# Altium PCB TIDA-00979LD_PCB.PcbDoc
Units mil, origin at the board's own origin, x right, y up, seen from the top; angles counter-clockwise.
Board outline 1000 x 1000 mil, 2 copper layers (Top Layer, Bottom Layer), stack 62 mil thick; 31 components, 45 nets, 126 pads, 53 vias.
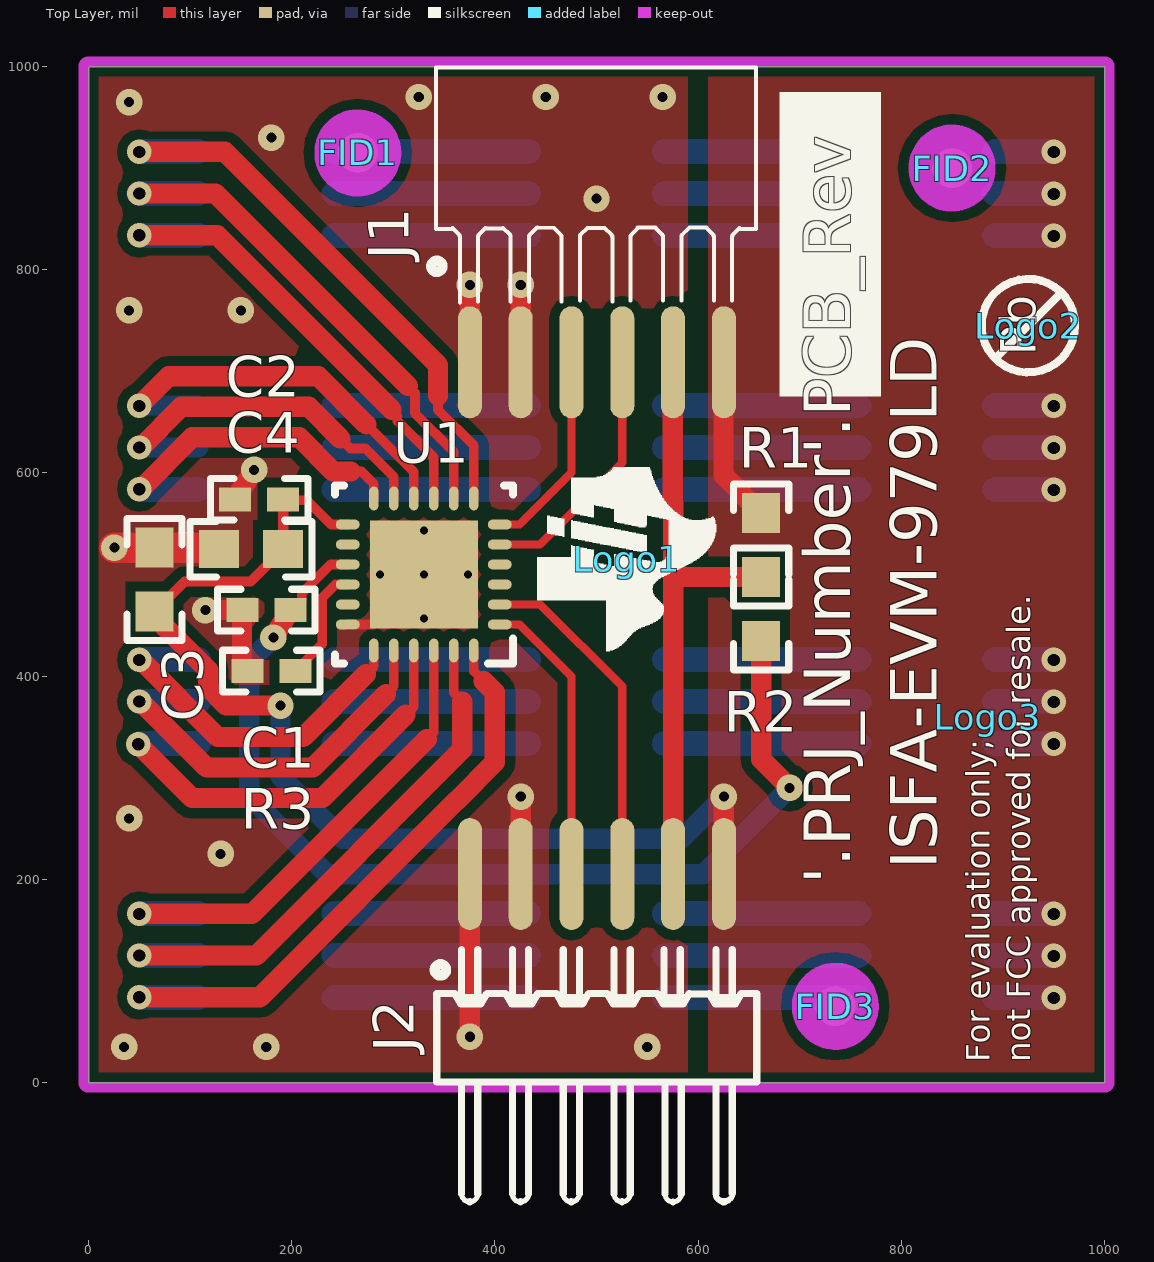
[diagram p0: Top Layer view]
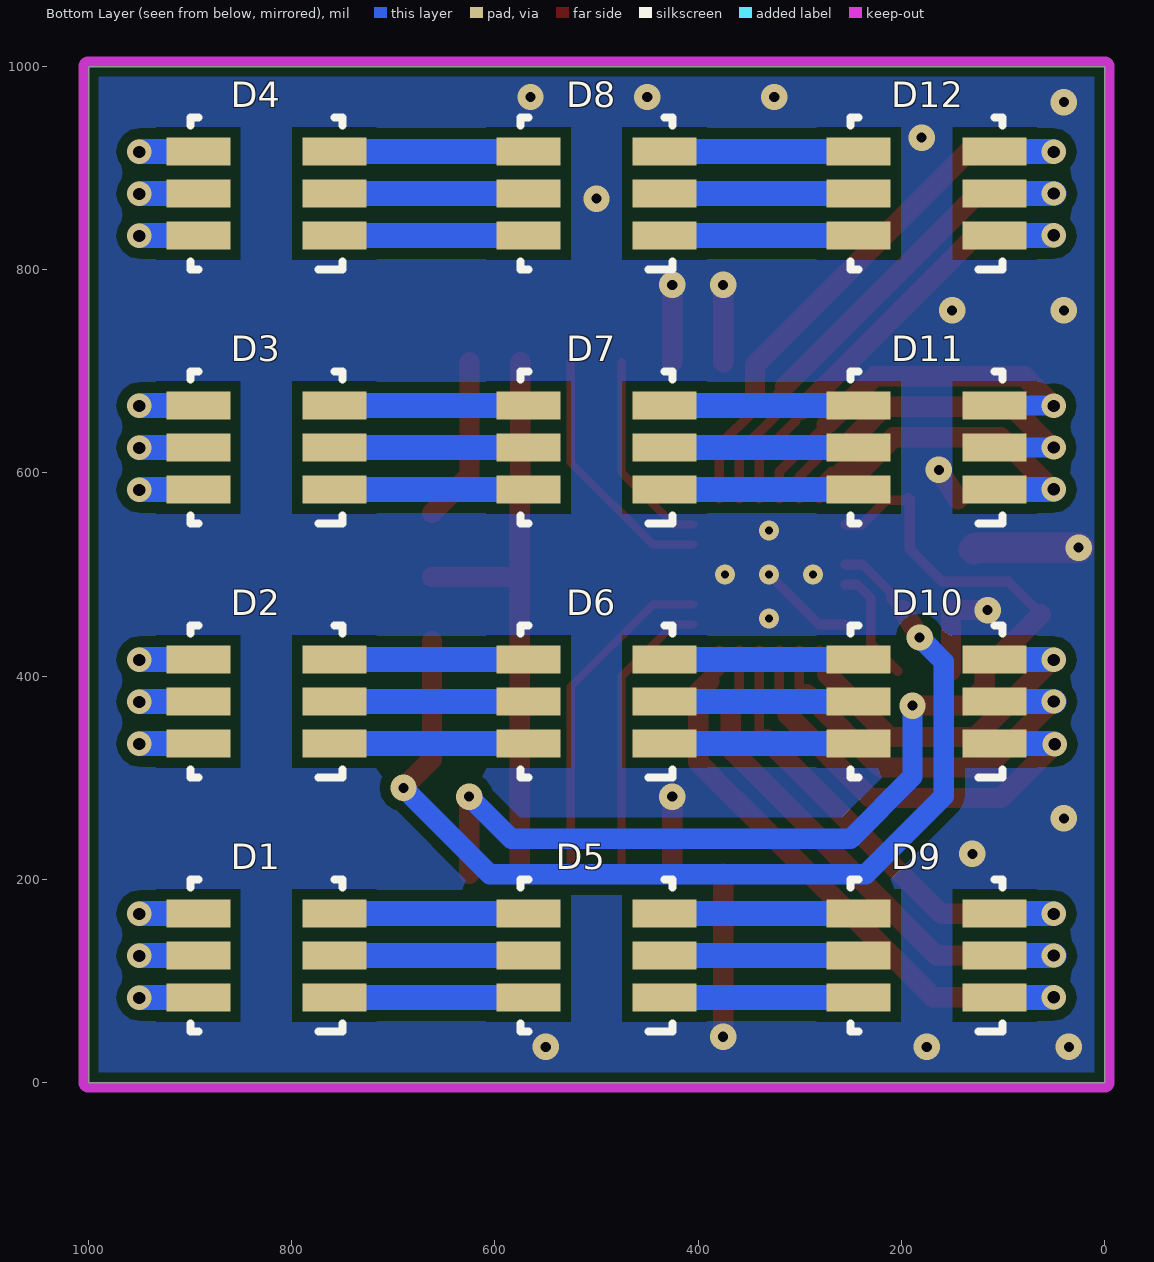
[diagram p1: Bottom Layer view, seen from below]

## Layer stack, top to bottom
Top Solder: solder mask 0.4, Solder Resist, Dk 3.5
Top Layer: signal copper 1.4
Dielectric1: core 59.2, FR-4, Dk 4.8
Bottom Layer: signal copper 1.4
Bottom Solder: solder mask 0.4, Solder Resist, Dk 3.5

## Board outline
0,0 1000,0 1000,1000 0,1000

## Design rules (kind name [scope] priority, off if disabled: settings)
AcuteAngle [All] p1: minimum=4.50000000000000E+0001 checktracksonly=FALSE
AssemblyTestPointUsage [All] p1: valid=2
Clearance Clearance_Keepouts [((IsTrack Or IsArc) And Not InPoly) And IsFree and IsKeepOut vs ((IsTrack Or IsArc) And Not InPoly) And IsFree and IsKeepOut] p1: gap=0
Clearance Clearance_Poly [InPolygon] p2: gap=25 except(10: Arc-Poly Track-Poly SMDPad-Poly Via-Poly Fill-Poly Poly-Poly)
Clearance [All] p3: gap=7.87
ComponentClearance ComponentClearance_3PIN_RES [incomponent('R1') or incomponent('R2') vs incomponent('R1') or incomponent('R2')] p1: gap=0 collisioncheckmode=3 verticalgap=0 showdistances=FALSE
ComponentClearance ComponentClearance_MountingHoles_FiducialMarks [InComponentClass('Mounting Holes') vs InComponentClass('FiducialMark')] p2: gap=50 collisioncheckmode=3 verticalgap=10 showdistances=FALSE
ComponentClearance ComponentClearance_Shunt [InComponentClass('Header') vs InComponentClass('Shunt')] p3: gap=0 collisioncheckmode=3 verticalgap=0 showdistances=FALSE
ComponentClearance ComponentClearance_Logo [InComponentClass('Logo')] p4: gap=25 collisioncheckmode=3 verticalgap=10 showdistances=FALSE
ComponentClearance ComponentClearance_ScrewToNut [(HasFootprint('NY PMS 440 0025 PH')) vs (HasFootprint('Keystone_1902C'))] p5: gap=5 collisioncheckmode=3 verticalgap=10 showdistances=FALSE
ComponentClearance ComponentClearance_MountingHoles [InComponentClass('Mounting Holes')] p6: gap=250 collisioncheckmode=3 verticalgap=100000 showdistances=FALSE
ComponentClearance ComponentClearance_SmallPassives [HasFootprint('0201*') or HasFootprint('0402*') or HasFootprint('0508') or HasFootprint('0603*') or HasFootprint('0612') or HasFootprint('0805*') or HasFootprint('0815*') or HasFootprint('0830*') or HasFootprint('1206*') or HasFootprint('1210*') or HasFootprint('1808*') or HasFootprint('1812*') or HasFootprint('1825*') or HasFootprint('2010*') or HasFootprint('2220*') or HasFootprint('2225*') or HasFootprint('2512*') or HasFootprint('2728*') or HasFootprint('3518*') vs HasFootprint('0201*') or HasFootprint('0402*') or HasFootprint('0508') or HasFootprint('0603*') or HasFootprint('0612') or HasFootprint('0805*') or HasFootprint('0815*') or HasFootprint('0830*') or HasFootprint('1206*') or HasFootprint('1210*') or HasFootprint('1808*') or HasFootprint('1812*') or HasFootprint('1825*') or HasFootprint('2010*') or HasFootprint('2220*') or HasFootprint('2225*') or HasFootprint('2512*') or HasFootprint('2728*') or HasFootprint('3518*')] p7: gap=14.96 collisioncheckmode=3 verticalgap=10 showdistances=FALSE
ComponentClearance ComponentClearance_THtoSMT [IsThruComponent vs IsSMTComponent] p8: gap=40 collisioncheckmode=3 verticalgap=30 showdistances=FALSE
ComponentClearance ComponentClearance_THtoTH [IsThruComponent vs IsThruComponent] p9: gap=30 collisioncheckmode=3 verticalgap=30 showdistances=FALSE
ComponentClearance [All] p10: gap=30 collisioncheckmode=3 verticalgap=10 showdistances=FALSE
DiffPairsRouting [All] p1: maxlimit=100 minlimit=10 mostfreqgap=10 toplayer_minwidth=15 toplayer_maxwidth=15 toplayer_prefwidth=15 bottomlayer_minwidth=15 bottomlayer_maxwidth=15 bottomlayer_prefwidth=15 maxuncoupledlength=1000
FabricationTestPointUsage TestPointUsage [All] p1: valid=2 allowmultiple=FALSE
FabricationTestpoint Testpoint [All] p1: side=3 testpointundercomponent=TRUE minsize=40 maxsize=100 preferedsize=60 minholesize=0 maxholesize=40 preferedholesize=32 testpointgrid=1 allowsidetop=TRUE allowsidebottom=TRUE usegrid=TRUE gridtolerance=0.01
FanoutControl Fanout_LCC [IsLCC] p1: bgadir=Out bgaviamode=Centered fanoutstyle=Auto fanoutdirection=Alternating viagrid=1 // Fanout_LCC (Default Rule)
FanoutControl Fanout_BGA [IsBGA] p2: bgadir=Out bgaviamode=Centered fanoutstyle=Auto fanoutdirection=Alternating viagrid=1 // Fanout_BGA (Default Rule)
FanoutControl Fanout_Default [All] p4: bgadir=Out bgaviamode=Centered fanoutstyle=Auto fanoutdirection=Alternating viagrid=1 // Fanout_Default (Default Rule)
FanoutControl Fanout_Small [(CompPinCount < 5)] p5: bgadir=Out bgaviamode=Centered fanoutstyle=Auto fanoutdirection=OutThenIn viagrid=1 // Fanout_Small (Default Rule)
HoleSize [All] p1: absolutevalues=TRUE maxlimit=251 minlimit=7.87 maxpercent=80.000 minpercent=20.000
MinimumAnnularRing MinimumAnnularRing_ThermalPadVias [IsVia and InAnyComponent] p1: minimumring=5.91
MinimumAnnularRing [All] p2: minimumring=6
MinimumSolderMaskSliver MinimumSolderMaskSliver_Logo [InComponentClass('Logo') vs InComponentClass('Logo')] p1: minsoldermaskwidth=0.7
MinimumSolderMaskSliver [All] p2: minsoldermaskwidth=3.94
PlaneConnect [All] p1: planeconnectstyle=Direct reliefexpansion=10 reliefentries=4 reliefconductorwidth=10 reliefairgap=10
PolygonConnect PolygonConnect_1 [All vs IsNamedPolygon('TOP_LAYER_NETD12_3_P002')] p1: connectstyle=Direct reliefconductorwidth=10 reliefentries=4 polygonreliefangle="90 Angle" airgapwidth=10
PolygonConnect [All] p2: connectstyle=Direct reliefconductorwidth=10 reliefentries=4 polygonreliefangle="90 Angle" airgapwidth=10
RoutingVias ThermalPadVias [IsVia and InAnyComponent] p1: holewidth=7.87 width=19.68 viastyle="Through Hole" minholewidth=7.87 minwidth=19.68 maxholewidth=12.99 maxwidth=23.62
RoutingVias [All] p2: holewidth=16 width=34 viastyle="Through Hole" minholewidth=7.87 minwidth=24 maxholewidth=40 maxwidth=65
SilkToBoardRegionClearance [Not ((IsComment or IsDesignator) And (Hide <> 'False')) and not InRegion(1000,500,4000,800)] p1:
SilkToSilkClearance SilkToSilkClearance_Pb-FreeLogo [(HasFootprint('Pb-Free_Overlay_Medium') OR HasFootprint('Pb-Free_Overlay_Small')) vs (HasFootprint('Pb-Free_Overlay_Medium') OR HasFootprint('Pb-Free_Overlay_Small'))] p1: silktosilkclearance=0
SilkToSilkClearance [All] p2: silktosilkclearance=4
SilkToSolderMaskClearance SilkToComponentPadClearance [IsPad and InAnycomponent] p1: minsilkscreentomaskgap=4.73 clearancetoexposedcopper=TRUE
SilkToSolderMaskClearance "Silk to Solder Mask Opening" [All] p2: minsilkscreentomaskgap=4 clearancetoexposedcopper=FALSE
SolderMaskExpansion [All] p1: expansion=1.97
Width [All] p1: maxlimit=100 minlimit=6 preferedwidth=10 checkconnectedcopper=TRUE
15 further rules are at their usual default settings.

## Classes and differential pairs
component class AssemblyNote: ZZ1 ZZ2 ZZ3
component class FiducialMark: FID1 FID2 FID3
component class TIDA-00979LD_CoverSheet: FID1 FID2 FID3 Logo1 Logo2 Logo3 ZZ1 ZZ2 ZZ3
component class Logo: Logo1
component class TIDA-00979LD_LEDdriver: C1 C2 C3 C4 D1 D2 D3 D4 D5 D6 D7 D8 D9 D10 D11 D12 J1 J2 R1 R2 R3 U1

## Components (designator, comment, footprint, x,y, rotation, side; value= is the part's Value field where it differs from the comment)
C1 "GRM155R70J105MA12D" 0402 175,465 r180 top
C2 "GRM155R71E104KE14D" 0402 168,574 r180 top
C3 "C1608X5R1E106M080AC" 0603 65,495 r90 top
C4 "C1608X5R1E106M080AC" 0603 160,525 r180 top
D1 "CLX6C-FKB-CGJKNCFBB789363" CLX6C-FKB_RGB 825,125 r0 bottom
D2 "CLX6C-FKB-CGJKNCFBB789363" CLX6C-FKB_RGB 825,375 r0 bottom
D3 "CLX6C-FKB-CGJKNCFBB789363" CLX6C-FKB_RGB 825,625 r0 bottom
D4 "CLX6C-FKB-CGJKNCFBB789363" CLX6C-FKB_RGB 825,875 r0 bottom
D5 "CLX6C-FKB-CGJKNCFBB789363" CLX6C-FKB_RGB 500,125 r0 bottom
D6 "CLX6C-FKB-CGJKNCFBB789363" CLX6C-FKB_RGB 500,375 r0 bottom
D7 "CLX6C-FKB-CGJKNCFBB789363" CLX6C-FKB_RGB 500,625 r0 bottom
D8 "CLX6C-FKB-CGJKNCFBB789363" CLX6C-FKB_RGB 500,875 r0 bottom
D9 "CLX6C-FKB-CGJKNCFBB789363" CLX6C-FKB_RGB 175,125 r0 bottom
D10 "CLX6C-FKB-CGJKNCFBB789363" CLX6C-FKB_RGB 175,375 r0 bottom
D11 "CLX6C-FKB-CGJKNCFBB789363" CLX6C-FKB_RGB 175,625 r0 bottom
D12 "CLX6C-FKB-CGJKNCFBB789363" CLX6C-FKB_RGB 175,875 r0 bottom
FID1 "Fiducial" Fiducial10-20 265,915 r0 top
FID2 "Fiducial" Fiducial10-20 850,900 r0 top
FID3 "Fiducial" Fiducial10-20 735,75 r0 top
J1 "851-11-006-40-001000" Mill-Max_851-11-006-40-001000 500.39,890 r90 top
J2 "850-10-006-40-001000" Mill-Max_850-10-006-40-001000 475,43.9 r0 top
Logo1 "Texas Instruments" TI_Symbol_Overlay_Small 530,515 r90 top
Logo2 "Pb-Free Symbol" Pb-Free_Overlay_Small 925,745 r90 top
Logo3 "FCC disclaimer" FCC_disclaimer_stacked 885,360 r90 top
R1 "CRCW06030000Z0EA" 0603 662,529 r90 top
R2 "CRCW06030000Z0EA" 0603 662,466 r270 top
R3 "CRCW04021K60JNED" 0402 180,405 r180 top
U1 "TLC5971RGER" RGE0024H 330,500 r180 top
ZZ1 "These assemblies are ESD sensitive, ESD precautions shall be observed." AssemblyNote 200,1350 r0 top
ZZ2 "These assemblies must be clean and free from flux and all contaminants. Use of no clean flux is not acceptable." AssemblyNote 200,1250 r0 top
ZZ3 "These assemblies must comply with workmanship standards IPC-A-610 Class 2, unless otherwise specified." AssemblyNote 200,1150 r0 top

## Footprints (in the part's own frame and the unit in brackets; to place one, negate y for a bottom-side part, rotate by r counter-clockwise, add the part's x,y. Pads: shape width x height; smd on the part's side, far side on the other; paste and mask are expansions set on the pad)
0402 [mm] "0402 from SM-752 data"
  rect 0.8x0.6 smd: 1(-0.6,0) 2(0.6,0)
  silkscreen extent -1.22,-0.52 1.22,0.52, body extent -0.55,-0.3 0.55,0.3, height 0.6
0603 [mm] "0603 from SM-752 data"
  rect 1x0.95 smd: 1(-0.8,0) 2(0.8,0)
  silkscreen extent -1.52,-0.69 1.52,0.69, body extent -0.87,-0.47 0.87,0.47, height 1
AssemblyNote [mil] "Assembly Note"
CLX6C-FKB_RGB [mm] "SMD, 6-Leads, Body 3.4x3.4mm"
  rect 1.6x0.7 smd: 1(-1.7,1.05) 2(-1.7,0) 3(-1.7,-1.05) 4(1.7,-1.05) 5(1.7,0) 6(1.7,1.05)
  silkscreen extent -1.9,-1.9 1.9,1.9, body extent -1.8,-1.75 1.8,1.75, height 2.9
FCC_disclaimer_stacked [mil]
Fiducial10-20 [mm]
  round 1 smd mask+0.5: 1(0,0)
  Top Layer keep-out circle w1.178: c0,0 r0.5
Mill-Max_850-10-006-40-001000 [mm] "Mill-max"
  oval 0.6x2.8 smd: 1(-2.53,4.1) 2(-1.26,4.1) 3(0.01,4.1) 4(1.28,4.1) 5(2.55,4.1) 6(3.82,4.1)
  silkscreen extent -3.41,-4.1 4.64,2.21, body extent -3.36,-4.08 4.64,5.44, height 2.15
Mill-Max_851-11-006-40-001000 [mm] "Mill-max"
  oval 2.8x0.6 smd: 1(-4.6,3.175) 2(-4.6,1.905) 3(-4.6,0.635) 4(-4.6,-0.635) 5(-4.6,-1.905) 6(-4.6,-3.175)
  silkscreen extent -3.1,-3.98 2.77,4.14, body extent -5.96,-4 2.77,4.01, height 2.03
Pb-Free_Overlay_Small [mil]
  silkscreen extent -46,-46 46,46
RGE0024H [mm] "QFN, 24-Leads, Body 4x4mm, Pitch 0.5mm, Thermal Pad 2.7x2.7mm, TI Recommended"
  oval 0.6x0.24 smd: 1(-1.9,1.25) 2(-1.9,0.75) 3(-1.9,0.25) 4(-1.9,-0.25) 5(-1.9,-0.75) 6(-1.9,-1.25) 13(1.9,-1.25) 14(1.9,-0.75) 15(1.9,-0.25) 16(1.9,0.25) 17(1.9,0.75) 18(1.9,1.25)
  oval 0.24x0.6 smd: 7(-1.25,-1.9) 8(-0.75,-1.9) 9(-0.25,-1.9) 10(0.25,-1.9) 11(0.75,-1.9) 12(1.25,-1.9) 19(1.25,1.9) 20(0.75,1.9) 21(0.25,1.9) 22(-0.25,1.9) 23(-0.75,1.9) 24(-1.25,1.9)
  rect 2.7x2.7 smd paste-1.35: 25(0,0)
  silkscreen extent -2.22,-2.22 2.22,2.22, body extent -2.07,-2.07 2.07,2.07, height 1.01
TI_Symbol_Overlay_Small [mil]
  silkscreen extent -90,-88 91,88

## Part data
C1: "CAP, CERM, 1 µF, 6.3 V, +/- 20%, X7R, 0402"
C2: "CAP, CERM, 0.1 µF, 25 V, +/- 10%, X7R, 0402"
C3 C4: "CAP, CERM, 10 µF, 25 V, +/- 20%, X5R, 0603"
D1 D2 D3 D4 D5 D6 D7 D8 D9 D10 D11 D12: "LED, Rgb, SMD"
FID1 FID2 FID3: "Fiducial mark.  There is nothing to buy or mount."
J1: "Receptacle, 50mil, 5x1, Gold, R/A, SMT"
J2: "Header, 50mil, 6x1, Gold, R/A, SMT"
Logo1: library part TI_Logo, "Texas Instrument Corporate Signature"
Logo2: library part Pb-Free
Logo3: library part FCC_disclaimer, "FCC_disclaimer"
R1 R2: "RES, 0, 5%, 0.1 W, 0603"
R3: "RES, 1.6 k, 5%, 0.063 W, 0402"
U1: "12-Channel, 16-Bit ES-PWM RGB LED Driver with 3.3 V Linear Regulator, 6 to 17 V, -40 to 85 degC, 24-pin QFN (RGE24), Green (RoHS & no Sb/Br)"
ZZ1 ZZ2 ZZ3: library part AssemblyNote

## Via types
v1: diameter 24, hole 12, Top Layer to Bottom Layer, tented both sides, 24 vias
v2: diameter 26, hole 10, Top Layer to Bottom Layer, tented both sides, 24 vias
v3: diameter 19.68, hole 7.87, Top Layer to Bottom Layer, 5 vias

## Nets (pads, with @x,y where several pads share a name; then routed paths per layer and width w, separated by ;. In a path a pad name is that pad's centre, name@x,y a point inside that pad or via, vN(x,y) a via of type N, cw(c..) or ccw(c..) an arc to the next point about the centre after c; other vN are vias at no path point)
GND: C1.2 C2.2 C3.2 C4.2 J1.1 J1.2 J2.1 J2.2 R3.2 U1.18 U1.25 | length 718.4
  Top Layer w9.5: U1.18 280.79,450.79 v3(330,500)
  Top Layer w20: v2(115,465) C1.2@151.13,465 ; C2.2 v2(163,603) ; R3.2@151.38,405 151.13,405.25 C1.2@151.13,465 ; C1.2 C1.2@151.13,465 ; v2(375.39,45) J2.1 ; J1.1 v2(375.39,785) ; J2.2 v2(425.39,281.42) ; J1.2 v2(425.39,785)
  Top Layer w30: v2(25.5,526.5) C3.2 127.01,526.5 C4.2
  other v2: 35,35 175,35 550,35 130,225 40,260 40,760 150,760 500,870 180,930 40,965 325,970 450,970 565,970
  other v3: 330,456.69 286.69,500 373.31,500 330,543.31
NetD1_1: D1.1 D5.6 | length 191.1
  Bottom Layer w25: D5.6 D1.1
NetD1_2: D1.2 D5.5 | length 191.1
  Bottom Layer w25: D5.5 D1.2
NetD1_3: D1.3 D5.4 | length 191.1
  Bottom Layer w25: D5.4 D1.3
NetD2_1: D2.1 D6.6 | length 191.1
  Bottom Layer w25: D6.6 D2.1
NetD2_2: D2.2 D6.5 | length 191.1
  Bottom Layer w25: D6.5 D2.2
NetD2_3: D2.3 D6.4 | length 191.1
  Bottom Layer w25: D6.4 D2.3
NetD3_1: D3.1 D7.6 | length 191.1
  Bottom Layer w25: D7.6 D3.1
NetD3_2: D3.2 D7.5 | length 191.1
  Bottom Layer w25: D7.5 D3.2
NetD3_3: D3.3 D7.4 | length 191.1
  Bottom Layer w25: D7.4 D3.3
NetD4_1: D4.1 D8.6 | length 191.1
  Bottom Layer w25: D8.6 D4.1
NetD4_2: D4.2 D8.5 | length 191.1
  Bottom Layer w25: D8.5 D4.2
NetD4_3: D4.3 D8.4 | length 191.1
  Bottom Layer w25: D8.4 D4.3
NetD5_1: D5.1 D9.6 | length 191.1
  Bottom Layer w25: D9.6 D5.1
NetD5_2: D5.2 D9.5 | length 191.1
  Bottom Layer w25: D9.5 D5.2
NetD5_3: D5.3 D9.4 | length 191.1
  Bottom Layer w25: D9.4 D5.3
NetD6_1: D6.1 D10.6 | length 191.1
  Bottom Layer w25: D10.6 D6.1
NetD6_2: D6.2 D10.5 | length 191.1
  Bottom Layer w25: D10.5 D6.2
NetD6_3: D6.3 D10.4 | length 191.1
  Bottom Layer w25: D10.4 D6.3
NetD7_1: D7.1 D11.6 | length 191.1
  Bottom Layer w25: D11.6 D7.1
NetD7_2: D7.2 D11.5 | length 191.1
  Bottom Layer w25: D11.5 D7.2
NetD7_3: D7.3 D11.4 | length 191.1
  Bottom Layer w25: D11.4 D7.3
NetD8_1: D8.1 D12.6 | length 191.1
  Bottom Layer w25: D12.6 D8.1
NetD8_2: D8.2 D12.5 | length 191.1
  Bottom Layer w25: D12.5 D8.2
NetD8_3: D8.3 D12.4 | length 191.1
  Bottom Layer w25: D12.4 D8.3
NetD9_1: D9.1 U1.24 | length 622.2
  Top Layer w9.5: U1.24 379.21,404.79 389,395
  Top Layer w20: v1(50,84) 168.79,84 363.1,278.31 363.31,278.31 400,315 400,384 389,395
  Bottom Layer w25: v1@50.34,83.66 D9.1
NetD9_2: D9.2 U1.23 | length 560.9
  Top Layer w9.5: U1.23 359.53,383.47 368,375
  Top Layer w20: v1(50,125) 165,125 368,328 368,375
  Bottom Layer w25: v1(50,125) D9.2
NetD9_3: D9.3 U1.22 | length 502
  Top Layer w9.5: 333,338 339.84,344.84 U1.22
  Top Layer w20: v1(50,166) 161,166 333,338
  Bottom Layer w25: v1@50.34,166.34 D9.3
NetD10_1: D10.1 U1.21 | length 443.2
  Top Layer w9.5: 312,362 320.16,370.16 U1.21
  Top Layer w20: v1(49,333) 102,280 230,280 312,362
  Bottom Layer w25: v1@50.34,333.66 D10.1
NetD10_2: D10.2 U1.20 | length 403.9
  Top Layer w9.5: 292.79,382.21 300.47,389.89 U1.20
  Top Layer w20: v1(50,375) 51.25,375 116.25,310 220.58,310 292.79,382.21
  Bottom Layer w25: v1(50,375) D10.2
NetD10_3: D10.3 U1.19 | length 364.4
  Top Layer w9.5: 273.08,401.92 280.79,409.63 U1.19
  Top Layer w20: v1(50,416) 51.25,416 127.25,340 211.16,340 273.08,401.92
  Bottom Layer w25: v1@50.34,416.34 D10.3
NetD11_1: D11.1 U1.12 | length 343
  Top Layer w9.5: 258,601.38 268.62,601.38 280.79,589.21 U1.12
  Top Layer w20: v1(50,584) 51.25,584 102.25,635 207.32,635 240.95,601.38 258,601.38
  Bottom Layer w25: v1@50.34,583.66 D11.1
NetD11_2: D11.2 U1.11 | length 375
  Top Layer w9.5: 247.87,633.87 257.74,624 272.59,624 300.47,596.12 U1.11
  Top Layer w20: v1(50,625) 51.25,625 91.25,665 216.74,665 247.87,633.87
  Bottom Layer w20: v1(50,625) D11.2
NetD11_3: D11.3 U1.10 | length 405
  Top Layer w9.5: 273.58,647.58 320.16,601 U1.10
  Top Layer w20: v1(50,666) 79,695 226.16,695 273.58,647.58
  Bottom Layer w20: v1@50.34,666.34 D11.3
NetD12_1: D12.1 U1.9 | length 481.8
  Top Layer w9.5: 298.29,662.29 304,656.58 304,651 339.84,615.16 U1.9
  Top Layer w20: v1(50,834) 126.58,834 298.29,662.29
  Bottom Layer w25: v1@50.34,833.66 D12.1
NetD12_2: D12.2 U1.8 | length 530.4
  Top Layer w9.5: 314.53,685.47 321.38,678.62 321.38,658.62 359.53,620.47 U1.8
  Top Layer w20: v1(50,875) 125,875 314.53,685.47
  Bottom Layer w25: v1(50,875) D12.2
NetD12_3: D12.3 U1.7 | length 584.5
  Top Layer w9.5: 344,676 344,662.03 379.21,626.82 U1.7
  Top Layer w20: v1(50,916) 134,916 344,706 344,676
  Bottom Layer w25: v1@50.34,916.34 D12.3
NetJ1_5: J1.5 J2.5 R1.1 R2.1 | length 590.4
  Top Layer w20: J1.5@575,708.9 575,570 575.39,569.61 J2.5 ; 575.39,497.5 R2.1
NetR3_1: R3.1 U1.16 | length 113.6
  Top Layer w9.5: R3.1 230,431.38 230,477 243.16,490.16 U1.16
SCK1: J2.4 U1.2 | length 338.4
  Top Layer w8: U1.2 444.53,470.47 525.39,389.61 J2.4
SCK2: J1.4 U1.5 | length 252.6
  Top Layer w8: U1.5 444.53,529.53 525.39,610.39 J1.4
SDT1: J2.3 U1.1 | length 286.1
  Top Layer w8: U1.1 424.21,450.79 475.39,399.61 J2.3
SDT2: J1.3 U1.6 | length 200.3
  Top Layer w8: U1.6 424.21,549.21 475.39,600.39 J1.3
VLED: C2.1 C3.1 C4.1 D1.4 D1.5 D1.6 D2.4 D2.5 D2.6 D3.4 D3.5 D3.6 D4.4 D4.5 D4.6 J1.6 J2.6 R1.2 U1.13 | length 1934.8
  Top Layer w8: J2.6 J2.6@627.2,203.5
  Top Layer w9.5: C2.1@191.62,573 215,573 238.79,549.21 U1.13
  Top Layer w10: C3.1 94.5,493 159.5,493 C4.1 191.62,525.13 C2.1@191.62,572.87 ; C2.1 191.62,573 C2.1@193.62,575
  Top Layer w20: C3.1@62.5,461 117.76,405.75 117.76,388.91 135.67,371 v2(189,371) ; J1.6@625,708.9 625,597.5 R1.2 ; J2.6 v2(625.39,281.42)
  Bottom Layer w20: v2(189,371) 189,301 250,240 583.98,240 v2(625.39,281.42)
  Bottom Layer w25: D1.6 v1@949.66,83.66 ; D1.5 v1@949.66,125 ; D1.4 v1@949.66,166.34 ; D2.6 v1@949.66,333.66 ; D2.5 v1@949.66,375 ; D2.4 v1@949.66,416.34 ; D3.6 v1@949.66,583.66 ; D3.5 v1@949.66,625 ; D3.4 v1@949.66,666.34 ; D4.6 v1@949.66,833.66 ; D4.5 v1@949.66,875 ; D4.4 v1@949.66,916.34
  other v1: 950,83.32 950,124.66 950,166 950,333.32 950,374.66 950,416 950,583.32 950,624.66 950,666 950,833.32 950,874.66 950,916
VREG: C1.1 R2.2 U1.15 | length 1031.5
  Top Layer w9.5: C1.1 199.63,465 210,475.37 210,481.57 238.27,509.84 U1.15
  Top Layer w20: v2(182,438) C1.1 ; R2.2 662,318 v2(690,290)
  Bottom Layer w20: v2(182,438) 158.13,414.13 158.13,281.87 235,205 605,205 v2(690,290)
pads on no net: FID1.1 FID2.1 FID3.1 U1.3 U1.4 U1.14 U1.17

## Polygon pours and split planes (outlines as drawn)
GND on Bottom Layer "Bottom Layer-No Net" (solid, remove dead copper, pour order 2): 0,0 1000,0 1000,1000 0,1000
VLED on Top Layer "Top Layer-No Net" (solid, remove dead copper, pour order 4): 610,0 1000,0 1000,1000 610,1000
GND on Top Layer "Top Layer-No Net 1" (solid, remove dead copper, pour order 6): 590,10 590,990 10,990 10,10

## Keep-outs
Keep-Out Layer:
  lines w10: -5,0 ccw(c0,0) 0,-5 ; -5,0 ccw(c0,0) 0,-5 ; -5,0 -5,1000 ; -5,1000 cw(c0,1000) 0,1005 ; -5,1000 cw(c0,1000) 0,1005 ; 0,-5 1000,-5 ; 0,1005 1000,1005 ; 1000,-5 ccw(c1000,0) 1005,0 ; 1000,-5 ccw(c1000,0) 1005,0 ; 1000,1005 cw(c1000,1000) 1005,1000 ; 1000,1005 cw(c1000,1000) 1005,1000 ; 1005,0 1005,1000
  text ".Layer_Name" at 577,-858.49 h60

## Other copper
Top Layer:
  text ".Layer_Name" at 577,-858.49 h60
Bottom Layer:
  text ".Layer_Name" at 577,-858.49 h60

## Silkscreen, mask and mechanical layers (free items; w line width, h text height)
Top Overlay:
  region: 680,975 680,675 780,675 780,975
  text "ISFA-EVM-979LD" at 850,210 h78.74 r90
  text "'.PRJ_Number'.PCB_Rev" at 765,195 h78.74 r90
  text ".Layer_Name" at 577,-858.49 h60
Bottom Overlay:
  text ".Layer_Name" at 577,-858.49 h60
Top Paste:
  text ".Layer_Name" at 577,-858.49 h60
Bottom Paste:
  text ".Layer_Name" at 577,-858.49 h60
Top Solder:
  text ".Layer_Name" at 577,-858.49 h60
  text ".Layer_Name" at 577,-858.49 h60
Bottom Solder:
  text ".Layer_Name" at 577,-858.49 h60
Drill Guide:
  text ".Layer_Name" at 577,-858.49 h60
M1 Board Outline:
  the board outline again, w10
  text ".Layer_Name" at 577,-858.49 h60
M2 Board Dimensions:
  rectangle: 125,-400 500,-275
  rectangle: 0,-275 125,-150
  lines w7: 0,-275 1000,-275 ; 125,-400 125,-150 ; 250,-400 250,-150 ; 500,-400 500,-150 ; 750,-400 750,-150 ; 0,-400 0,-150 1000,-150 1000,-400 0,-400
  text ".Layer_Name" at 577,-858.49 h60
M3 3D STEP Top:
  text ".Layer_Name" at 577,-858.49 h60
M4 3D STEP Bottom:
  text ".Layer_Name" at 577,-858.49 h60
M5 Assembly Top:
  lines w10: -292,-930.17 6308,-930.17 ; -292,-726.83 6310,-726.83 ; -292,-523.5 -292,-1133.5 3713,-1133.5 6310,-1133.5 6310,-523.5 -291.5,-523.5 -291.5,-1133.5 1284,-1133.5 ; 2173,-1133.5 2173,-523.5 ; 3440,-726.83 3440,-523.5 ; 4280,-726.83 4280,-523.5 ; 4902,-1140 4902,-937.17
  text "COMPONENTS MARKED 'DNP' SHOULD NOT BE POPULATED." at 1153.5,-318.5 h60
  text "ASSEMBLY VARIANT:" at 1153,-434 h60
  text ".VariantName" at 2189,-434 h60
  text "PCB VIEWED FROM TOP SIDE" at -228.5,-655.67 h60
  text "BOARD #:" at 2248,-655.67 h60
  text ".PRJ_Number" at 2793.5,-655.67 h60
  text "REV:" at 3638,-655.67 h60
  text ".PCB_Rev" at 3929.5,-655.67 h60
  text "SVN REV:" at 4476,-655.67 h60
  text ".VersionControl_RevNumber" at 4982,-655.67 h60
  text "TID #:" at 2248,-859 h60
  text ".TID" at 2793.5,-859 h60
  text "PLOT NAME =" at -228.5,-1064.34 h60
  text ".plot_File_Name" at 577,-1064.34 h60
  text "GENERATED    :" at 2250,-1064.34 h60
  text ".Print_Date" at 3119.5,-1064.34 h60
  text ".Print_Time" at 3848.5,-1064.34 h60
  text "TEXAS INSTRUMENTS" at 5113,-1064.34 h60
M6 Assembly Bottom:
  lines w10: -292.5,-727.33 6309.5,-727.33 ; -290.5,-930.67 6309.5,-930.67 ; 1115.5,-1140.5 1115.5,-937.67 ; 1737.5,-727.33 1737.5,-524 ; 2577.5,-727.33 2577.5,-524 ; 3844.5,-1134 3844.5,-524 ; 4733.5,-1134 6309,-1134 6309,-524 -292.5,-524 -292.5,-1134 2304.5,-1134 6309.5,-1134 6309.5,-524
  text "COMPONENTS MARKED 'DNP' SHOULD NOT BE POPULATED." at 6102,-318 h60
  text ".VariantName" at 5058,-434 h60
  text "ASSEMBLY VARIANT:" at 6097,-434 h60
  text ".VersionControl_RevNumber" at 1035.5,-656.17 h60
  text "SVN REV:" at 1541.5,-656.17 h60
  text ".PCB_Rev" at 2088,-656.17 h60
  text "REV:" at 2379.5,-656.17 h60
  text ".PRJ_Number" at 3224,-656.17 h60
  text "BOARD #:" at 3769.5,-656.17 h60
  text "PCB VIEWED FROM BOTTOM SIDE" at 6246,-656.17 h60
  text ".TID" at 3224,-859.5 h60
  text "TID #:" at 3769.5,-859.5 h60
  text "TEXAS INSTRUMENTS" at 904.5,-1064.84 h60
  text ".Print_Time" at 2169,-1064.84 h60
  text ".Print_Date" at 2898,-1064.84 h60
  text "GENERATED    :" at 3767.5,-1064.84 h60
  text ".plot_File_Name" at 5440.5,-1064.84 h60
  text "PLOT NAME =" at 6246,-1064.84 h60
M9 Title Sheet:
  drawing of 57 lines, arcs and shapes, not listed
  text "1" at 739.84,8036.5 h70
  text "2" at 3235.5,8036.5 h70
  text "3" at 5724.84,8036.5 h70
  text "4" at 8231.51,8036.5 h70
  text "5" at 10730.5,8036.5 h70
  text "6" at 13235.5,8036.5 h70
  text "A" at -416.5,6893.5 h70
  text "A" at 14383.5,6893.5 h70
  text "B" at -416.5,4513.5 h70
  text "B" at 14383.5,4513.5 h70
  text "C" at -416.5,2138.5 h70
  text "C" at 14383.5,2138.5 h70
  text "PROJECT TITLE:" at 11343.5,277.5 h45
  text ".PRJ_Title" at 11393.5,144.17 h70
  text "DESIGNED FOR:" at 11343.5,-23.5 h45
  text ".PRJ_Customer" at 11393.5,-163.5 h70
  text "D" at -416.5,-231.5 h70
  text "D" at 14383.5,-231.5 h70
  text "FILE NAME:" at 11343.5,-323.5 h45
  text ".PCB_File_Name_No_Path" at 11393.5,-443.5 h70
  text "Texas Instruments (TI) and/or its licensors do not warrant the accuracy or completeness of this specification" at 6374,-605.34 h45
  text "ENGINEER:" at 11343.5,-613.5 h45
  text "LAYOUT BY:" at 12848.5,-613.5 h45
  text "or any information contained therein. TI and/or its licensors do not warrant that this design will meet" at 6329.01,-718 h45
  text ".PRJ_Engineer" at 11393.5,-768.49 h70
  text ".PCB_Layout" at 12899,-768.49 h70
  text "the specifications, will be suitable for your application or fit for any particular purpose, or will operate in" at 6329.01,-830.67 h45
  text ".Layer_Name" at 577,-858.49 h60
  text "ALTIUM DESIGNER VERSION:" at 12848.5,-923.5 h45
  text "an implementation. TI and/or its licensors do not warrant that the design is production worthy. You should" at 6329.01,-943.33 h45
  text "completely validate and test your design implementation to confirm the system functionality for your application." at 6374,-1056 h45
  text ".print_Scale" at 11393.5,-1056.83 h70
  text ".Application_BuildNumber" at 12899,-1056.83 h70
  text "1" at 739.84,-1263.5 h70
  text "2" at 3235.5,-1263.5 h70
  text "3" at 5724.84,-1263.5 h70
  text "4" at 8231.51,-1263.5 h70
  text "5" at 10730.5,-1263.5 h70
  text "6" at 13235.5,-1263.5 h70
M10 Fab Notes:
  drawing of 173 lines, arcs and shapes, not listed
  text "DESIGN INFORMATION" at 12378.02,6201 h60
  text "MIN. TRACK WIDTH:" at 11733.46,6021 h60
  text "8" at 12829.7,6021 h60
  text "MIL" at 12984.46,6021 h60
  text "MIN. CLEARANCE:" at 11733.46,5889 h60
  text "0.2" at 12769.7,5889 h60
  text "mm" at 12984.46,5889 h60
  text "MIN. VIA PAD SIZE:" at 11733.46,5757 h60
  text "24" at 12799.71,5757 h60
  text "MIL" at 12984.46,5757 h60
  text "0.05mm (2MIL)" at 12428.46,5615.29 h60
  text "MINIMUM ANNULAR RING" at 11404.23,5611 h60
  text "EXTERNAL" at 13136.46,5611 h60
  text "PER" at 11604.23,5493 h60
  text "IPC-D-275 CLASS 2 LEVEL C" at 11824.23,5493 h60
  text "MIL, HOLES" at 13312.46,5380.71 h60
  text "+/-" at 12920,5380 h60
  text "+/-" at 13774,5380 h60
  text "REGISTRATION TOLERANCES:" at 11404.23,5375 h60
  text "METAL" at 12604,5375 h60
  text "5" at 13180.2,5375 h60
  text "3" at 14013.2,5375 h60
  text "MIL" at 14129.46,5375 h60
  text "+/-" at 13774,5262 h60
  text "HOLE SIZE TOLERANCE (UNLESS OTHERWISE SPECIFIED):" at 11404.23,5257 h60
  text "3" at 14013.2,5257 h60
  text "MIL" at 14129.46,5257 h60
  text "MATERIAL:" at 11329.46,5047.54 h60
  text "FR-4 High Tg" at 12315.9,4907.21 h60
  text "FR-408" at 11750.46,4898.64 h60
  text "OTHER" at 13238.46,4898.64 h60
  text "X" at 12161,4895 h60
  text "62 MIL (1.6mm) +/-10%" at 12070.56,4735.92 h60
  text "THICKNESS:" at 11404.23,4731.64 h60
  text "X" at 11942.4,4731.64 h60
  text "OTHER" at 13355.46,4731.64 h60
  text "TOLERANCE:" at 11404.23,4573.64 h60
  text "X" at 12243.53,4573.64 h60
  text "ANSI IPC-6012 TYPE 3 CLASS 2" at 12430.48,4573.64 h60
  text "OTHER +/-" at 12430.46,4417.64 h60
  text "BOW & TWIST:" at 11404.23,4260.64 h60
  text "X" at 12243.53,4260.64 h60
  text "ANSI IPC-6012 TYPE 3 CLASS 2" at 12430.48,4260.64 h60
  text "OTHER +/-" at 12430.46,4102.13 h60
  text "DRILLING:" at 11329.46,3963.64 h60
  text "REFERENCE:" at 11404.23,3846.64 h60
  text "X" at 12052.46,3846.64 h60
  text "AS SHOWN" at 12239.46,3846.64 h60
  text "X" at 12953.46,3846.64 h60
  text "NC_DRILL FILES" at 13090.46,3846.64 h60
  text "PTH MIN COPPER THICKNESS:" at 11404.23,3688.64 h60
  text "X" at 12754.46,3688.64 h60
  text "1MIL" at 12891.46,3688.64 h60
  text "OTHER" at 13388.46,3688.64 h60
  text "BOARD FINISH:" at 11329.46,3529.64 h60
  text "SILKSCREEN:" at 11484.68,3411.64 h60
  text "X" at 12433.46,3411.64 h60
  text "TOP" at 12559.46,3411.64 h60
  text "X" at 12943.46,3411.64 h60
  text "BOTTOM" at 13070.46,3411.64 h60
  text "SILKSCREEN COLOR:" at 11484.68,3244.64 h60
  text "X" at 12432.42,3244.64 h60
  text "WHITE" at 12559.46,3244.64 h60
  text "OTHER" at 13070.46,3244.64 h60
  text "X" at 12563.42,3085.44 h60
  text "GREEN" at 12690.46,3085.44 h60
  text "OTHER" at 13308.46,3085.44 h60
  text "SOLDER RESIST COLOR:" at 11484.68,3074.64 h60
  text "X" at 12563.42,2915.44 h60
  text "MATTE" at 12690.46,2915.44 h60
  text "SEMI-GLOSS" at 13308,2914.8 h60
  text "IMMERSION GOLD (ENIG)" at 12390.46,2726.92 h60
  text "ENEPIG" at 13728,2723.64 h60
  text "SURFACE FINISH:" at 11329.46,2722.64 h60
  text "X" at 12203.51,2722.64 h60
  text "IMM. TIN/SILVER OR EQUIV" at 11659,2565.64 h60
  text "OTHER" at 13090.46,2565.64 h60
  text "ARRAY/PANEL:" at 11329.46,2386.64 h60
  text "CUT AND TRIM PER M1 BOARD OUTLINE" at 12390.46,2382.35 h60
  text "N.C. ROUTE" at 12390.46,2230.64 h60
  text "X" at 13069.46,2230.64 h60
  text "V. SCORE" at 13256.46,2230.64 h60
  text "CERTIFICATION:" at 11329.46,2093.64 h60
  text "MATERIALS AND WORKMANSHIP FOR ALL PCBS" at 12054.46,2093.64 h60
  text "TO MEET OR EXCEED THE REQUIREMENTS OF:" at 12054.46,1995.64 h60
  text "X" at 11680.96,1859.13 h60
  text "ANSI IPC-A-600F CLASS ->" at 11819.96,1859.13 h60
  text "X" at 13459.02,1859.13 h60
  text "2" at 13577.96,1859.14 h60
  text "1" at 13262.96,1857.64 h60
  text "3" at 13931.96,1857.64 h60
  text "X" at 12495.02,1699.64 h60
  text "RoHS" at 12631.96,1699.64 h60
  text "OTHER" at 13276.36,1699.64 h60
  text "PER ORDER" at 13673.42,1699.64 h60
  text "ALL BOARDS MUST MEET OR EXCEED UL94-V0 REQUIREMENTS." at 11357,1534 h60
  text "PCB MUST BEAR THE UL94V-0 UL REGISTERED MATERIAL ID NUMBER" at 11357,1414 h60
  text "ADDITIONAL REQUIREMENTS:" at 11329.46,1240.64 h60
  text "MICROSECTION:" at 11404.23,1125.64 h60
  text "YES" at 12309.96,1125.64 h60
  text "REQUIRED" at 13171.46,969.49 h60
  text "BARE BOARD ELEC. TEST:" at 11404.23,966.64 h60
  text "NONE" at 12709.96,966.64 h60
  text "X" at 13044.46,966.64 h60
  text "PER ORDER" at 13763.46,966.64 h60
  text ".Layer_Name" at 577,-858.49 h60
M11 Gerber Information:
  lines w10: -292,-930.17 6308,-930.17 ; -292,-726.83 6310,-726.83 ; -292,-523.5 -292,-1133.5 3713,-1133.5 6310,-1133.5 6310,-523.5 -291.5,-523.5 -291.5,-1133.5 1284,-1133.5 ; 2173,-1133.5 2173,-523.5 ; 3440,-726.83 3440,-523.5 ; 4280,-726.83 4280,-523.5 ; 4902,-1140 4902,-937.17
  text "ALL ARTWORK VIEWED FROM TOP SIDE" at -228.5,-655.67 h60
  text "BOARD #:" at 2248,-655.67 h60
  text ".PRJ_Number" at 2793.5,-655.67 h60
  text "REV:" at 3638,-655.67 h60
  text ".PCB_Rev" at 3929.5,-655.67 h60
  text "SVN REV:" at 4476,-655.67 h60
  text ".VersionControl_RevNumber" at 4982,-655.67 h60
  text "LAYER NAME =" at -228.5,-858.49 h60
  text "TID #:" at 2248,-859 h60
  text ".TID" at 2793.5,-859 h60
  text "PLOT NAME =" at -228.5,-1064.34 h60
  text ".plot_File_Name" at 577,-1064.34 h60
  text "GENERATED    :" at 2250,-1064.34 h60
  text ".Print_Date" at 3119.5,-1064.34 h60
  text ".Print_Time" at 3848.5,-1064.34 h60
  text "TEXAS INSTRUMENTS" at 5113,-1064.34 h60
M12 Stackup:
  drawing of 191 lines, arcs and shapes, not listed
  text "Layer" at 9790.34,7830 h60
  text "Name" at 10200.26,7830 h60
  text "Material" at 11130,7830 h60
  text "Thickness" at 11989.77,7830 h60
  text "Constant" at 12639.6,7830 h60
  text "Board Layer Stack" at 13209.46,7830 h60
  text "1" at 9790.34,7710 h60
  text "Top Overlay" at 10200.26,7710 h60
  text "2" at 9790.34,7590 h60
  text "Top Solder" at 10200.26,7590 h60
  text "Solder Resist" at 11130,7590 h60
  text "0.40mil" at 11989.77,7590 h60
  text "3.5" at 12639.6,7590 h60
  text "3" at 9790.34,7470 h60
  text "Top Layer" at 10200.26,7470 h60
  text "Copper" at 11130,7470 h60
  text "1.40mil" at 11989.77,7470 h60
  text "4" at 9790.34,7350 h60
  text "Dielectric1" at 10200.26,7350 h60
  text "FR-4" at 11130,7350 h60
  text "59.20mil" at 11989.77,7350 h60
  text "4.8" at 12639.6,7350 h60
  text "5" at 9790.34,7230 h60
  text "Bottom Layer" at 10200.26,7230 h60
  text "Copper" at 11130,7230 h60
  text "1.40mil" at 11989.77,7230 h60
  text "6" at 9790.34,7110 h60
  text "Bottom Solder" at 10200.26,7110 h60
  text "Solder Resist" at 11130,7110 h60
  text "0.40mil" at 11989.77,7110 h60
  text "3.5" at 12639.6,7110 h60
  text "7" at 9790.34,6990 h60
  text "Bottom Overlay" at 10200.26,6990 h60
  text ".Layer_Name" at 577,-858.49 h60
M13 Component Bodies Top:
  text ".Layer_Name" at 577,-858.49 h60
M14 Component Bodies Bottom:
  text ".Layer_Name" at 577,-858.49 h60
M15 Courtyards Top:
  text ".Layer_Name" at 577,-858.49 h60
M16 Courtyards Bottom:
  text ".Layer_Name" at 577,-858.49 h60
Drill Drawing:
  circle w10: c5363.82,3017.02 r27.67
  lines w10: 5336.16,3127.68 5349.99,3127.68 5349.99,3113.85 5377.66,3113.85 5377.66,3127.68 5391.49,3127.68 5391.49,3155.35 5377.66,3155.35 5377.66,3169.18 5349.99,3169.18 5349.99,3155.35 5336.16,3155.35 5336.16,3127.68 ; 5336.16,3238.35 5391.49,3238.35 5391.49,3293.68 5336.16,3293.68 5336.16,3238.35
  lines w12: 5286,2952 8363.99,2952 ; 5286,3325.5 8363.99,3325.5 ; 5624.01,2827.5 5624.01,3450 ; 5956.17,2827.5 5956.17,3450 ; 6592.65,2827.5 6592.65,3450 ; 6851.85,2827.5 6851.85,3450 ; 7227.09,2827.5 7227.09,3450 ; 7951.64,2827.5 7951.64,3450 ; 5286,2827.5 8363.99,2827.5 8363.99,3450 5286,3450 5286,2827.5
  text "Symbol" at 5360.7,3362.85 h72
  text "Quantity" at 5661.36,3362.85 h72
  text "Finished Hole Size" at 5993.52,3362.85 h72
  text "Plated" at 6630,3362.85 h72
  text "Hole Type" at 6889.2,3362.85 h72
  text "Drill Layer Pair" at 7264.44,3362.85 h72
  text "Tolerance" at 7988.99,3362.85 h72
  text "5" at 5661.36,3238.35 h60
  text "7,87mil (0,200mm)" at 5993.52,3238.35 h60
  text "PTH" at 6630,3238.35 h60
  text "Round" at 6889.2,3238.35 h60
  text "Top Layer - Bottom Layer" at 7264.44,3238.35 h60
  text "24" at 5661.36,3113.85 h60
  text "10,00mil (0,254mm)" at 5993.52,3113.85 h60
  text "PTH" at 6630,3113.85 h60
  text "Round" at 6889.2,3113.85 h60
  text "Top Layer - Bottom Layer" at 7264.44,3113.85 h60
  text "24" at 5661.36,2989.35 h60
  text "12,00mil (0,305mm)" at 5993.52,2989.35 h60
  text "PTH" at 6630,2989.35 h60
  text "Round" at 6889.2,2989.35 h60
  text "Top Layer - Bottom Layer" at 7264.44,2989.35 h60
  text "53 Total" at 5661.36,2864.85 h60
  text ".Layer_Name" at 577,-858.49 h60
M17 Embedded Cavity:
  text ".Layer_Name" at 577,-858.49 h60
M18 Embedded Assembly:
  text ".Layer_Name" at 577,-858.49 h60
M19 Embedded Keepout:
  text ".Layer_Name" at 577,-858.49 h60

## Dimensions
0,0 to 1000,0 on M2 Board Dimensions
0,0 to 0,1000 on M2 Board Dimensions
0,-400 to 1000,-400 on M2 Board Dimensions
